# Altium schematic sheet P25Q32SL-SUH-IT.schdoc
size 127 x 101 mm
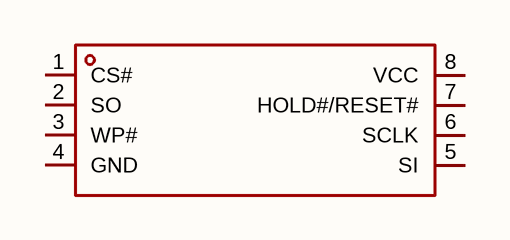
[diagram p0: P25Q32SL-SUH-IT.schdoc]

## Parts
U?  p25q32sl-suh-it  [SOP-8_L5.3-W5.3-P1.27-LS8.0-BL]  (value not drawn)

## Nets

Not connected (* = marked no-connect by the designer): U? 1(CS#) 2(SO) 3(WP#) 4(GND) 5(SI) 6(SCLK) 7(HOLD#/RESET#) 8(VCC)

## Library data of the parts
U? = p25q32sl-suh-it: 接口类型:SPI;存储容量:32Mbit;时钟频率(fc):85MHz;; Manufacturer: PUYA(普冉); AddInBom: yes; ModelId: e456afcfff5840a795bdd4917416584f; ModelName: SOP-8_L5.2-W5.3-H2.1-LS7.9-P1.27; ModelTransform: 311.024,204.724,0,90,0,0,0,0.0005,0; Interface: SPI; Memory Size: 32Mbit; Clock Frequency: 85MHz; Voltage - Supply: 1.65V~2V; Standby Supply Current: 9uA; Program / Erase Cycles: 100000次; Write Cycle Time (tWC): 12ms; Page Programming Time (Tpp): 1.6ms; Block Erase Time(tBE): 16ms; Data Retention - TDR (Year): 20年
